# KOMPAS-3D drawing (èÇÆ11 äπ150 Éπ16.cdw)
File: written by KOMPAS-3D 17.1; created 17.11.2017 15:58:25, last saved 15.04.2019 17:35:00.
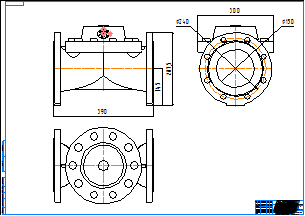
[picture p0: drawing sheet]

Sheet 1: A0, landscape

Title block, sheet 1: name: КАТ11 Ду150 Ру16; material: Внимание! Данный продукт является объектом авторского права ООО «Торговый Дом АДЛ». / Запрещается изменение, копирование, распространение / (в том числе путем копирования на другие сайты и ресурсы в Интернете) / или любое иное использование информации и объектов без предварительного / согласия правообладателя (ООО «Торговый Дом АДЛ»).; mass: 12,4; sheets: 1; organisation: ООО "Торговый дом АДЛ"; sheet format: A0; stored path: \\adlc.lan\data\АДЛ_ПКД\3D-модели\ADL production\Клапаны КАТ ГРАНРЕГ\КАТ11\KOMPAS 2D\КАТ11 Ду150 Ру16.cdw

Views: Вид 1, Проекционный вид 2, Проекционный вид 3
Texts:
  kka
  adl
Dimensions and other numbers on the sheet: 390; 145; 287,5; 240; 300; 150; 1:1; 1; 12,4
